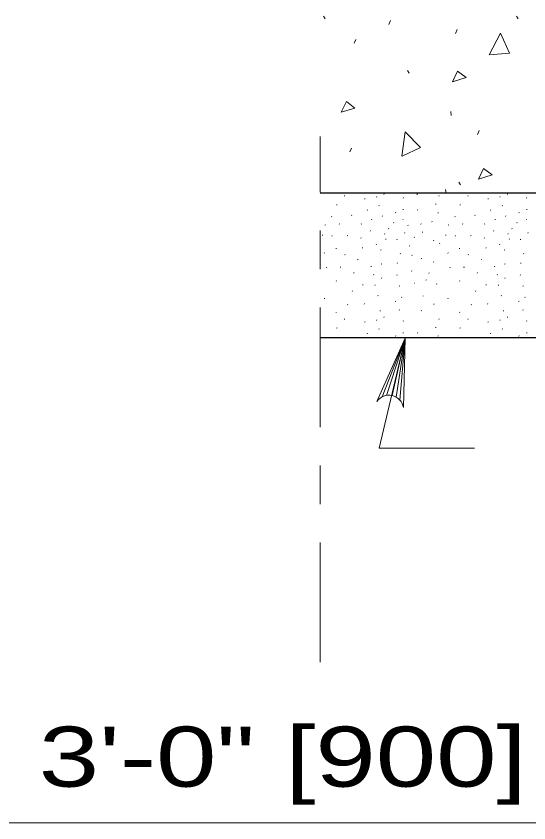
# Model space of a CAD drawing. Extents: x 1083.1 to 1117.1, y 719.4 to 763.4.
# Drawn here: x 1093.658 to 1094.987, y 726.642 to 728.736 of the extents above; entities that cross this region are included whole.
import ezdxf
from ezdxf.enums import TextEntityAlignment as Align

# ---------------------------------------------------------------- set-up
doc = ezdxf.new("R2010")
doc.units = 0
doc.header["$LTSCALE"] = 0.062
doc.linetypes.add('DOT_DASHED', pattern=[7.7, 5, -1.2, 0.3, -1.2])
doc.layers.add('1', color=7, linetype='Continuous', lineweight=13)

msp = doc.modelspace()

# ---------------------------------------------------------------- linework, layer by layer
at = {"layer": '1'}
for p, q in [((1094.45508, 728.73642), (1094.4595, 728.72975)), ((1094.955, 728.73642), (1094.95942, 728.72975)), ((1094.62392, 728.71467), (1094.62833, 728.72467)), ((1094.79708, 728.6915), (1094.8015, 728.7015)), ((1094.534, 728.66592), (1094.53842, 728.67592)), ((1094.67275, 728.59492), (1094.67717, 728.58825)), ((1094.78492, 728.4885), (1094.78608, 728.4785)), ((1094.85417, 728.42958), (1094.85858, 728.43958)), ((1094.52283, 728.38408), (1094.52733, 728.39408)), ((1094.80542, 728.30533), (1094.80992, 728.29867)), ((1094.45508, 728.27708), (1094.45533, 728.27658)), ((1094.50908, 728.26875), (1094.50967, 728.27042)), ((1094.6115, 728.27367), (1094.61208, 728.27533)), ((1094.69725, 728.2755), (1094.69892, 728.27383)), ((1094.75392, 728.26875), (1094.75442, 728.27042)), ((1094.77325, 728.27658), (1094.77133, 728.28642)), ((1094.82908, 728.26875), (1094.82967, 728.27042)), ((1094.9315, 728.27367), (1094.93208, 728.27533)), ((1094.955, 728.27708), (1094.95533, 728.27658)), ((1094.56275, 728.26242), (1094.56108, 728.26208)), ((1094.59208, 728.26642), (1094.59267, 728.26808)), ((1094.66158, 728.26408), (1094.66217, 728.26575)), ((1094.74708, 728.2485), (1094.74533, 728.24817)), ((1094.88275, 728.26242), (1094.88108, 728.26208)), ((1094.91208, 728.26642), (1094.91267, 728.26808)), ((1094.98158, 728.26408), (1094.98217, 728.26575)), ((1094.48992, 728.247), (1094.48817, 728.24658)), ((1094.56808, 728.23158), (1094.56858, 728.23325)), ((1094.59875, 728.24367), (1094.59792, 728.2445)), ((1094.66258, 728.23458), (1094.66083, 728.23425)), ((1094.69883, 728.23317), (1094.69942, 728.23483)), ((1094.80992, 728.247), (1094.80817, 728.24658)), ((1094.88808, 728.23158), (1094.88858, 728.23325)), ((1094.91875, 728.24367), (1094.91792, 728.2445)), ((1094.98258, 728.23458), (1094.98083, 728.23425)), ((1094.47642, 728.21558), (1094.4755, 728.21642)), ((1094.52825, 728.21892), (1094.52742, 728.21975)), ((1094.57967, 728.20767), (1094.58025, 728.20933)), ((1094.60683, 728.21642), (1094.60742, 728.21808)), ((1094.64217, 728.22558), (1094.64133, 728.22633)), ((1094.66133, 728.20808), (1094.6605, 728.20892)), ((1094.75325, 728.22608), (1094.75158, 728.22575)), ((1094.79633, 728.21558), (1094.7955, 728.21642)), ((1094.84825, 728.21892), (1094.84742, 728.21975)), ((1094.89967, 728.20767), (1094.90025, 728.20933)), ((1094.92683, 728.21642), (1094.92742, 728.21808)), ((1094.96217, 728.22558), (1094.96133, 728.22633)), ((1094.98133, 728.20808), (1094.9805, 728.20892)), ((1094.45967, 728.19475), (1094.45808, 728.19392)), ((1094.49633, 728.19642), (1094.4955, 728.19725)), ((1094.55258, 728.196), (1094.55308, 728.19767)), ((1094.63717, 728.19975), (1094.63633, 728.20058)), ((1094.67467, 728.19308), (1094.67383, 728.19392)), ((1094.708, 728.19642), (1094.70717, 728.19725)), ((1094.73633, 728.20225), (1094.7355, 728.20308)), ((1094.77967, 728.19475), (1094.778, 728.19392)), ((1094.81633, 728.19642), (1094.8155, 728.19725)), ((1094.87258, 728.196), (1094.87308, 728.19767)), ((1094.95717, 728.19975), (1094.95633, 728.20058)), ((1094.45183, 728.16717), (1094.45242, 728.16883)), ((1094.47658, 728.16542), (1094.47708, 728.16708)), ((1094.51783, 728.16683), (1094.51608, 728.16642)), ((1094.57583, 728.178), (1094.57642, 728.17967)), ((1094.61308, 728.17033), (1094.61358, 728.172)), ((1094.62317, 728.18475), (1094.62383, 728.18442)), ((1094.62383, 728.18442), (1094.62417, 728.184)), ((1094.66475, 728.17342), (1094.66533, 728.17508)), ((1094.71125, 728.17492), (1094.71183, 728.17658)), ((1094.77175, 728.16717), (1094.77233, 728.16883)), ((1094.79658, 728.16542), (1094.79708, 728.16708)), ((1094.83783, 728.16683), (1094.83608, 728.16642)), ((1094.89583, 728.178), (1094.89642, 728.17967)), ((1094.93308, 728.17033), (1094.93358, 728.172)), ((1094.94317, 728.18475), (1094.94383, 728.18442)), ((1094.94383, 728.18442), (1094.94417, 728.184)), ((1094.98475, 728.17342), (1094.98533, 728.17508)), ((1094.55225, 728.15967), (1094.55142, 728.1605)), ((1094.59133, 728.143), (1094.59192, 728.14458)), ((1094.61617, 728.15633), (1094.61675, 728.158)), ((1094.64533, 728.15608), (1094.64592, 728.15775)), ((1094.69083, 728.162), (1094.69, 728.16283)), ((1094.73992, 728.153), (1094.7405, 728.15467)), ((1094.75675, 728.1465), (1094.75592, 728.14733)), ((1094.87225, 728.15967), (1094.87142, 728.1605)), ((1094.91133, 728.143), (1094.91192, 728.14458)), ((1094.93617, 728.15633), (1094.93675, 728.158)), ((1094.96533, 728.15608), (1094.96592, 728.15775)), ((1094.48833, 728.13358), (1094.48658, 728.13317)), ((1094.55567, 728.13442), (1094.55625, 728.13608)), ((1094.60467, 728.12967), (1094.60292, 728.12933)), ((1094.67792, 728.13908), (1094.6785, 728.14075)), ((1094.80833, 728.13358), (1094.80658, 728.13317)), ((1094.87567, 728.13442), (1094.87625, 728.13608)), ((1094.92467, 728.12967), (1094.92292, 728.12933)), ((1094.45767, 728.121), (1094.45683, 728.12183)), ((1094.51117, 728.11708), (1094.51033, 728.11792)), ((1094.54492, 728.10492), (1094.54325, 728.10458)), ((1094.65433, 728.11942), (1094.6535, 728.12025)), ((1094.68458, 728.11475), (1094.68375, 728.11558)), ((1094.70817, 728.10658), (1094.70867, 728.10825)), ((1094.77767, 728.121), (1094.77683, 728.12183)), ((1094.83117, 728.11708), (1094.83033, 728.11792)), ((1094.86492, 728.10492), (1094.86325, 728.10458)), ((1094.97433, 728.11942), (1094.9735, 728.12025)), ((1094.46267, 728.08342), (1094.46325, 728.08508)), ((1094.5, 728.08483), (1094.49825, 728.08442)), ((1094.57817, 728.08567), (1094.57867, 728.08733)), ((1094.60625, 728.09333), (1094.6045, 728.09292)), ((1094.64608, 728.09425), (1094.64667, 728.09592)), ((1094.74117, 728.09775), (1094.74033, 728.09858)), ((1094.78258, 728.08342), (1094.78317, 728.08508)), ((1094.82, 728.08483), (1094.81825, 728.08442)), ((1094.89817, 728.08567), (1094.89867, 728.08733)), ((1094.92625, 728.09333), (1094.9245, 728.09292)), ((1094.96608, 728.09425), (1094.96667, 728.09592)), ((1094.53317, 728.06942), (1094.53375, 728.07108)), ((1094.58558, 728.0645), (1094.58475, 728.06533)), ((1094.6455, 728.06433), (1094.64467, 728.06517)), ((1094.68383, 728.07458), (1094.683, 728.07542)), ((1094.72833, 728.06867), (1094.72883, 728.07033)), ((1094.85317, 728.06942), (1094.85375, 728.07108)), ((1094.90558, 728.0645), (1094.90475, 728.06533)), ((1094.9655, 728.06433), (1094.96467, 728.06517)), ((1094.48867, 728.04825), (1094.48783, 728.04908)), ((1094.55733, 728.03917), (1094.55567, 728.03883)), ((1094.58825, 728.037), (1094.58875, 728.03867)), ((1094.60533, 728.05575), (1094.60583, 728.05742)), ((1094.69083, 728.04283), (1094.69, 728.04367)), ((1094.72225, 728.05158), (1094.72058, 728.05117)), ((1094.74892, 728.0405), (1094.74808, 728.04133)), ((1094.80867, 728.04825), (1094.80783, 728.04908)), ((1094.87733, 728.03917), (1094.87567, 728.03883)), ((1094.90825, 728.037), (1094.90875, 728.03867)), ((1094.92533, 728.05575), (1094.92583, 728.05742)), ((1094.52925, 728.0215), (1094.52983, 728.02317)), ((1094.653, 728.03608), (1094.65133, 728.03525)), ((1094.84925, 728.0215), (1094.84983, 728.02317)), ((1094.973, 728.03608), (1094.97133, 728.03525)), ((1094.45717, 728.00292), (1094.45775, 728.00458)), ((1094.59642, 728.01033), (1094.59558, 728.01117)), ((1094.658, 728.00617), (1094.65717, 728.007)), ((1094.71283, 728.00908), (1094.71333, 728.01075)), ((1094.77717, 728.00292), (1094.77775, 728.00458)), ((1094.91642, 728.01033), (1094.91558, 728.01117)), ((1094.978, 728.00617), (1094.97717, 728.007)), ((1094.51817, 727.98708), (1094.51733, 727.98792)), ((1094.56033, 727.989), (1094.56083, 727.99067)), ((1094.64217, 727.99617), (1094.6405, 727.99533)), ((1094.74167, 727.98892), (1094.73992, 727.9885)), ((1094.83817, 727.98708), (1094.83733, 727.98792)), ((1094.88033, 727.989), (1094.88083, 727.99067)), ((1094.96217, 727.99617), (1094.9605, 727.99533)), ((1094.48742, 727.96667), (1094.488, 727.96833)), ((1094.60233, 727.97183), (1094.60058, 727.9715)), ((1094.6115, 727.95375), (1094.61208, 727.95542)), ((1094.65217, 727.97292), (1094.65133, 727.97375)), ((1094.70867, 727.97175), (1094.70783, 727.9725)), ((1094.80742, 727.96667), (1094.808, 727.96833)), ((1094.92233, 727.97183), (1094.92058, 727.9715)), ((1094.9315, 727.95375), (1094.93208, 727.95542)), ((1094.97217, 727.97292), (1094.97133, 727.97375)), ((1094.50908, 727.94883), (1094.50967, 727.9505)), ((1094.56275, 727.9425), (1094.56108, 727.94217)), ((1094.59208, 727.9465), (1094.59267, 727.94817)), ((1094.66158, 727.94417), (1094.66217, 727.94583)), ((1094.75392, 727.94883), (1094.75442, 727.9505)), ((1094.82908, 727.94883), (1094.82967, 727.9505)), ((1094.88275, 727.9425), (1094.88108, 727.94217)), ((1094.91208, 727.9465), (1094.91267, 727.94817)), ((1094.98158, 727.94417), (1094.98217, 727.94583)), ((1094.48992, 727.92708), (1094.48817, 727.92667)), ((1094.56808, 727.91167), (1094.56858, 727.91333)), ((1094.59875, 727.92375), (1094.59792, 727.92458)), ((1094.66258, 727.91467), (1094.66083, 727.91433)), ((1094.69883, 727.91325), (1094.69942, 727.91492)), ((1094.74708, 727.92858), (1094.74533, 727.92825)), ((1094.80992, 727.92708), (1094.80817, 727.92667)), ((1094.88808, 727.91167), (1094.88858, 727.91333)), ((1094.91875, 727.92375), (1094.91792, 727.92458)), ((1094.98258, 727.91467), (1094.98083, 727.91433)), ((1094.60658, 727.74783), (1094.66617, 727.90075)), ((1094.61808, 727.75158), (1094.66617, 727.90075)), ((1094.63275, 727.75125), (1094.66617, 727.90075)), ((1094.64217, 727.90567), (1094.64133, 727.90642)), ((1094.6435, 727.74717), (1094.66617, 727.90075)), ((1094.65308, 727.73942), (1094.66617, 727.90075)), ((1094.75325, 727.90617), (1094.75158, 727.90583)), ((1094.96217, 727.90567), (1094.96133, 727.90642)), ((1092.19642, 726.64225), (1094.55033, 726.64225)), ((1096.69617, 726.64225), (1094.55033, 726.64225))]:
    msp.add_line(p, q, dxfattribs=at)
at = {"layer": '1', "linetype": 'DOT_DASHED'}
msp.add_line((1094.44633, 727.05983), (1094.44633, 728.42417), dxfattribs=at)
at = {"layer": '1', "lineweight": 25}
for p, q in [((1097.44608, 728.27658), (1094.44633, 728.27658)), ((1097.44608, 727.90158), (1094.44633, 727.90158))]:
    msp.add_line(p, q, dxfattribs=at)
at = {"layer": '1'}
for points in [[(1094.88408, 728.636), (1094.91408, 728.69258), (1094.93742, 728.64042), (1094.88525, 728.636)], [(1094.65792, 728.37258), (1094.66675, 728.43608), (1094.7065, 728.395), (1094.65892, 728.373)], [(1094.593, 727.73567), (1094.66617, 727.90075), (1094.66217, 727.72025)], [(1094.66617, 727.90075), (1094.5995, 727.61467), (1094.8465, 727.61467)]]:
    msp.add_lwpolyline(points, dxfattribs=at)
for points in [[(1094.78925, 728.56608), (1094.80258, 728.59383), (1094.82483, 728.57717)], [(1094.50092, 728.48675), (1094.51425, 728.5145), (1094.53642, 728.49792)], [(1094.85633, 728.31308), (1094.86967, 728.34083), (1094.89192, 728.32417)]]:
    msp.add_lwpolyline(points, close=True, dxfattribs=at)
msp.add_arc((1094.6245, 727.71399), 0.03822, 9.50414, 145.33026, dxfattribs=at)

# ---------------------------------------------------------------- texts
at = {"layer": '1', "width": 1.35}
msp.add_text('3\'-0" [900]', height=0.156, dxfattribs=at).set_placement((1094.34912, 726.73617), align=Align.CENTER)

doc.saveas('drawing.dxf')
